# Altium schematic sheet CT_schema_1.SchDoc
size 596 x 258 mm
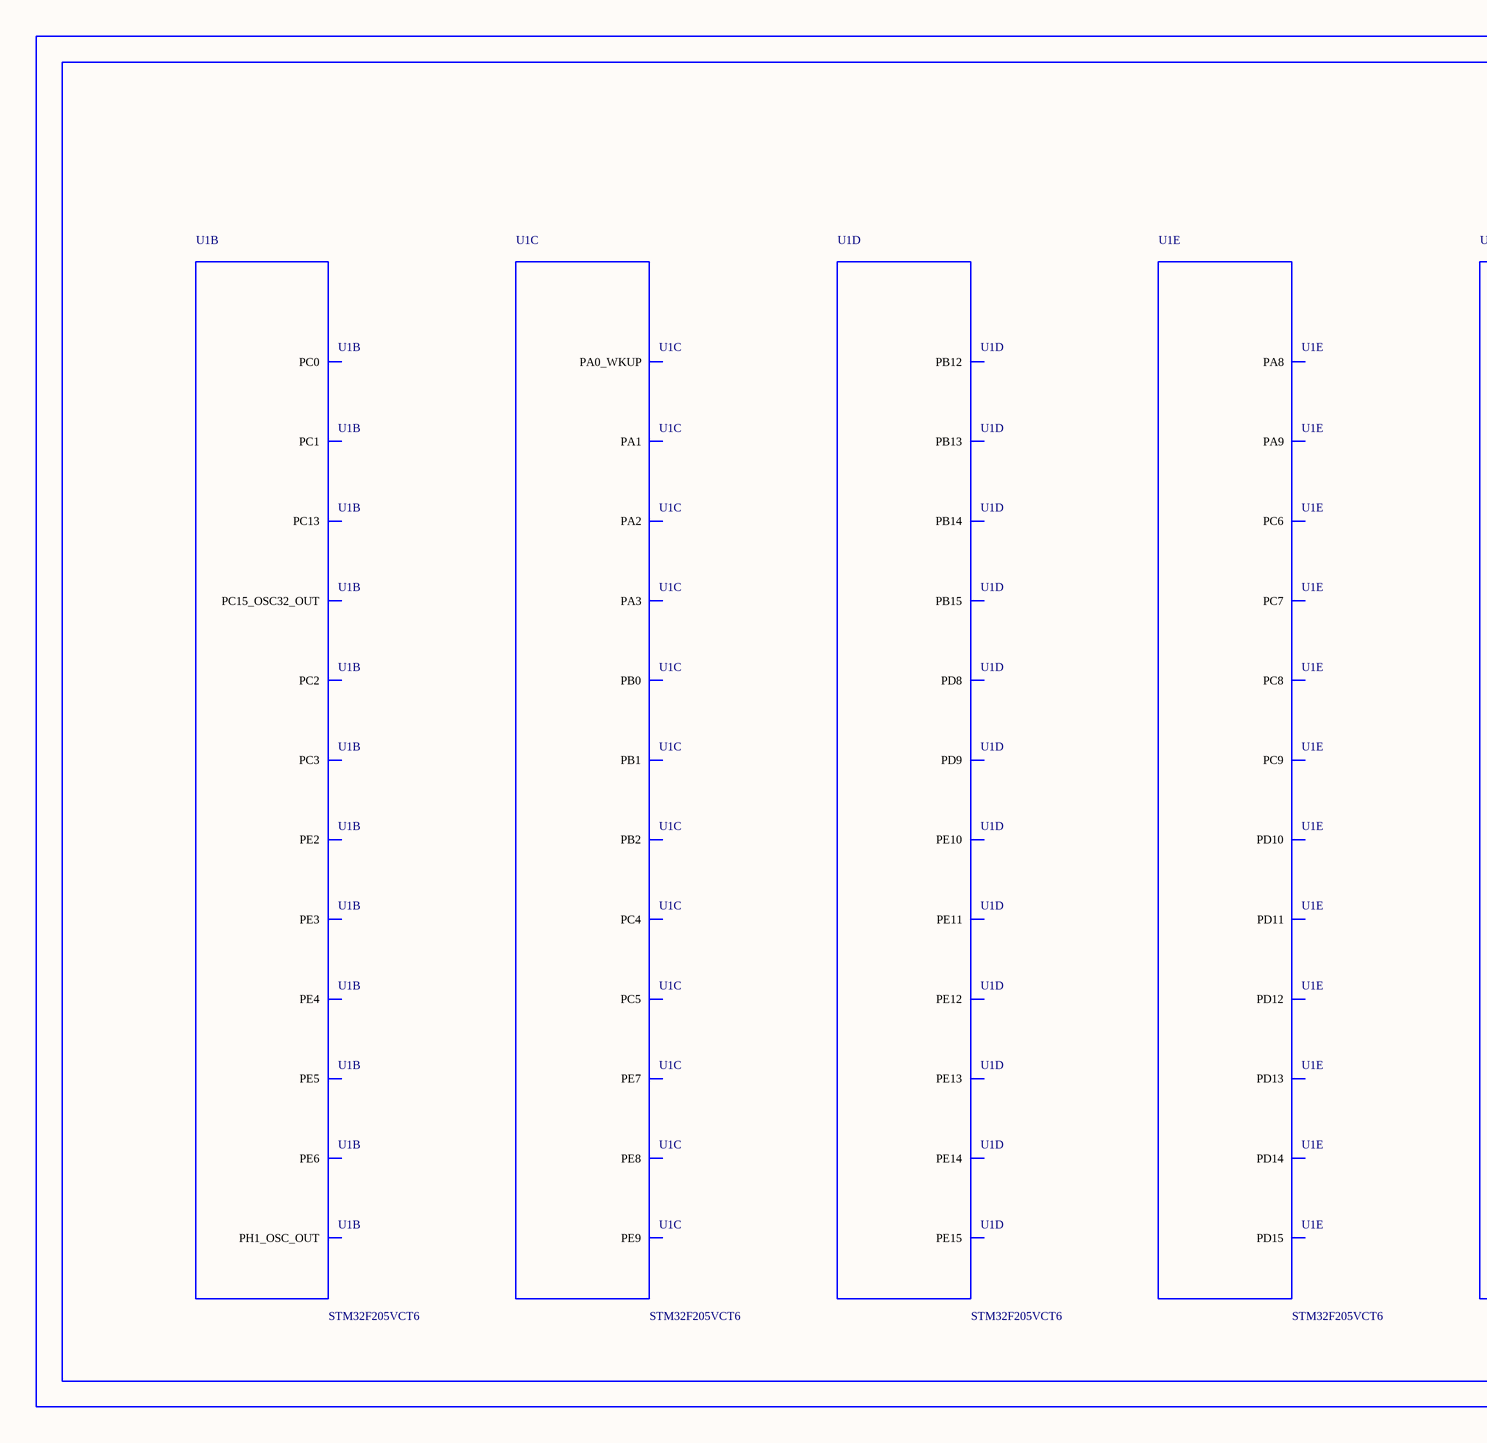
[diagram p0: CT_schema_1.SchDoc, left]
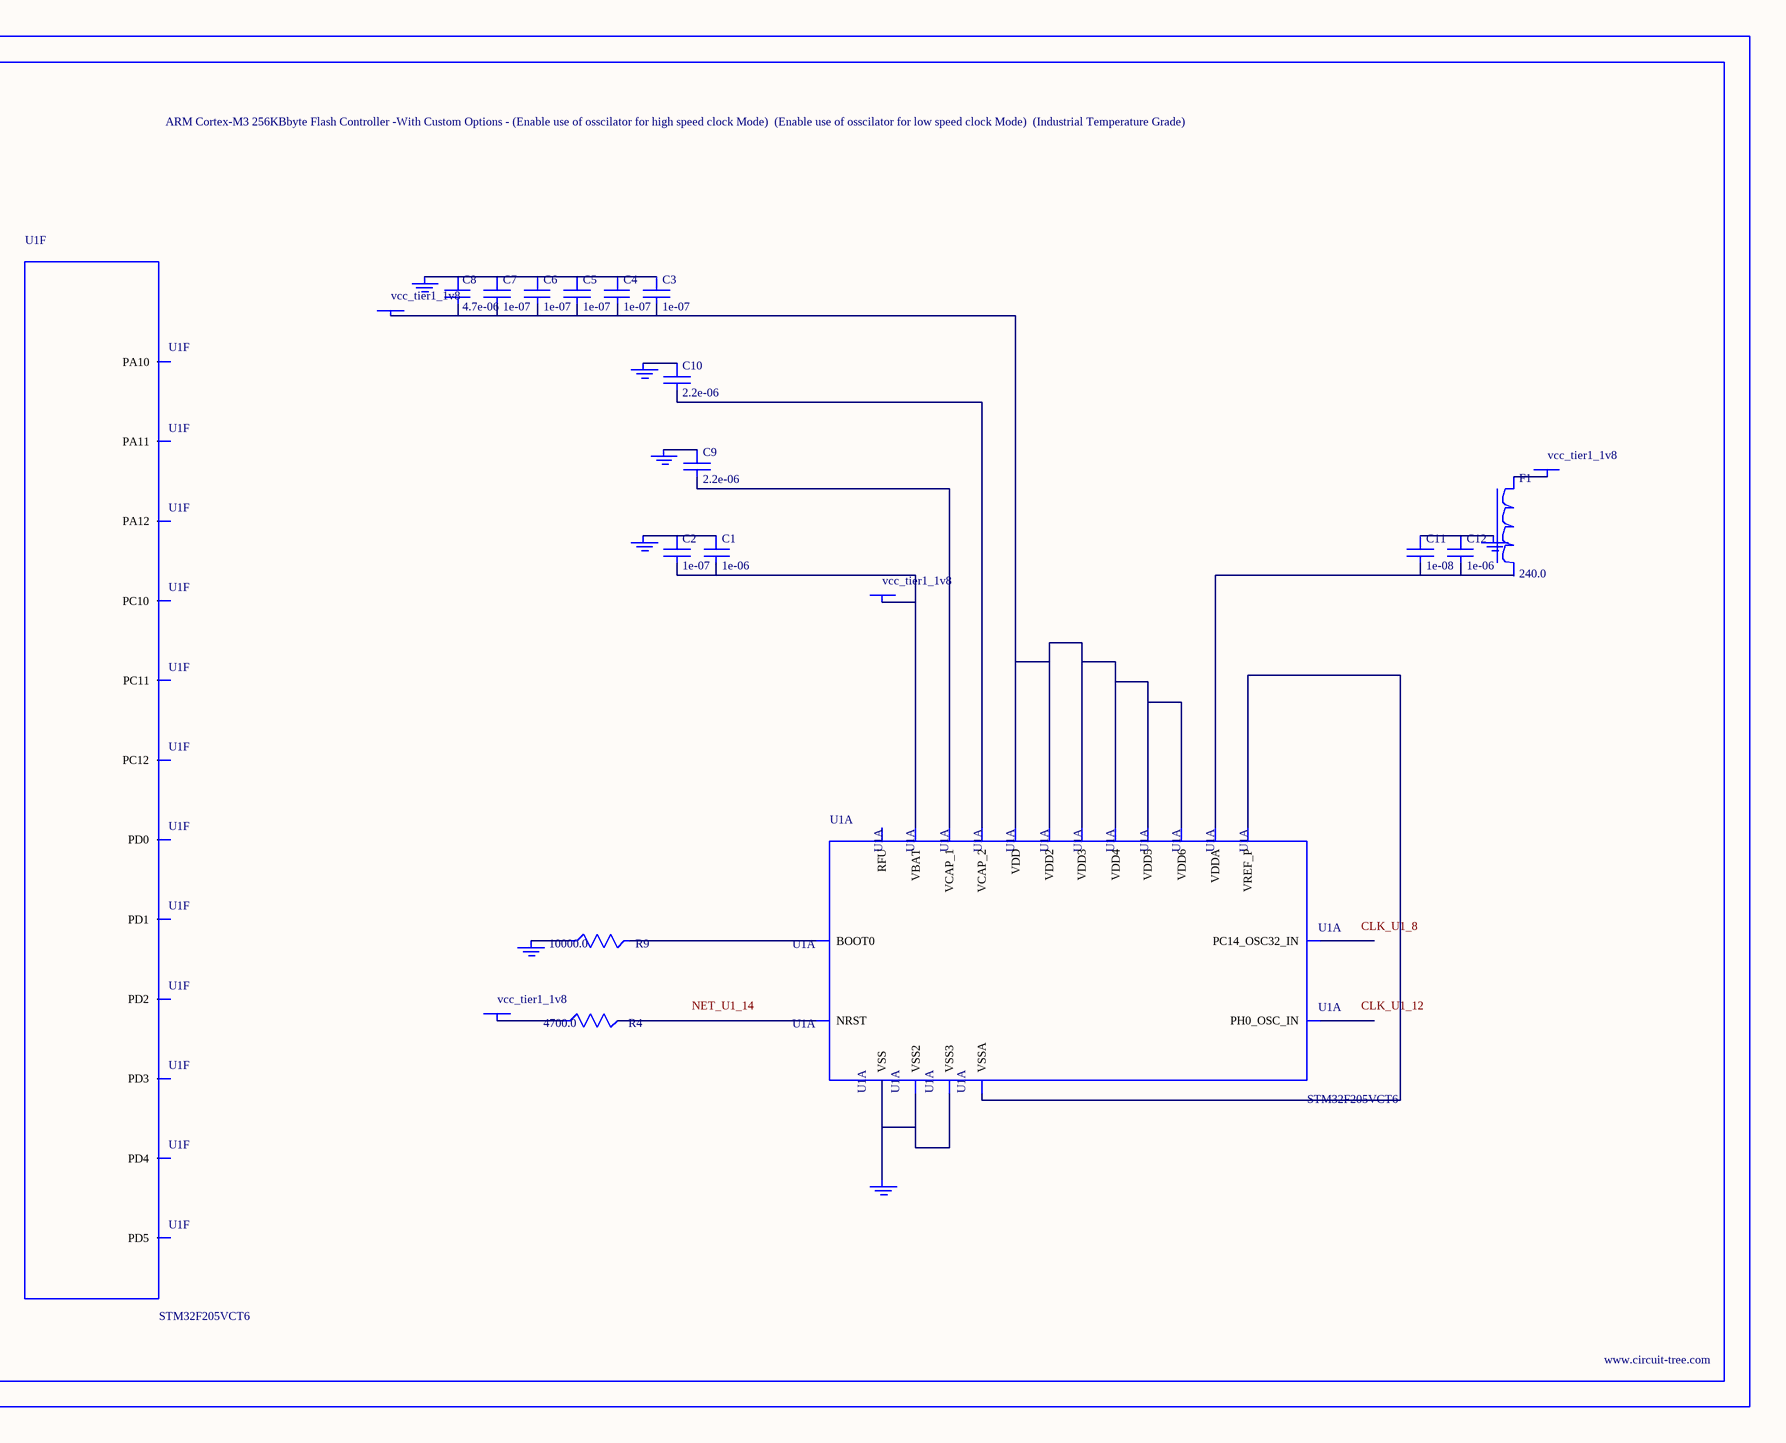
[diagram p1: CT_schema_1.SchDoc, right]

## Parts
BORDER0  (no value)
C1  1e-06  [C0603]
C2  1e-07  [C0603]
C3  1e-07  [C0603]
C4  1e-07  [C0603]
C5  1e-07  [C0603]
C6  1e-07  [C0603]
C7  1e-07  [C0603]
C8  4.7e-06  [C0603]
C9  2.2e-06  [C0603]
C10  2.2e-06  [C0603]
C11  1e-08  [C0603]
C12  1e-06  [C0603]
F1  240.0  [L0603]
GND_INSTANCE_0_0  (no value)
GND_INSTANCE_0_1  (no value)
GND_INSTANCE_0_2  (no value)
GND_INSTANCE_0_3  (no value)
GND_INSTANCE_0_4  (no value)
GND_INSTANCE_0_5  (no value)
GND_INSTANCE_0_6  (no value)
POWER_INSTANCE_0_0  vcc_tier1_1v8
POWER_INSTANCE_0_1  vcc_tier1_1v8
POWER_INSTANCE_0_2  vcc_tier1_1v8
POWER_INSTANCE_0_3  vcc_tier1_1v8
R4  4700.0  [R0603]
R9  10000.0  [R0603]
U1  STM32F205VCT6  [LQFP100]  (parts A,B,C,D,E,F of 10)

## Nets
NetC1_1: C1.1 C2.1 GND_INSTANCE_0_0.0(GND)
NetC1_2: C1.2 C2.2 POWER_INSTANCE_0_0.0(PWR) U1.6(VBAT)
NetC3_1: C3.1 C4.1 C5.1 C6.1 C7.1 C8.1 GND_INSTANCE_0_1.0(GND)
NetC3_2: C3.2 C4.2 C5.2 C6.2 C7.2 C8.2 POWER_INSTANCE_0_1.0(PWR) U1.11(VDD) U1.19(VDD2) U1.28(VDD3) U1.50(VDD4) U1.75(VDD5) U1.100(VDD6)
NetC9_1: C9.1 GND_INSTANCE_0_3.0(GND)
NetC9_2: C9.2 U1.49(VCAP_1)
NetC10_1: C10.1 GND_INSTANCE_0_4.0(GND)
NetC10_2: C10.2 U1.73(VCAP_2)
NetC11_1: C11.1 C12.1 GND_INSTANCE_0_2.0(GND)
NetC11_2: C11.2 C12.2 U1.22(VDDA)
NetF1_1: F1.1 POWER_INSTANCE_0_2.0(PWR)
NetGND_INSTANCE_0_5_0: GND_INSTANCE_0_5.0(GND) R9.1
NetGND_INSTANCE_0_6_0: GND_INSTANCE_0_6.0(GND) U1.10(VSS) U1.27(VSS2) U1.74(VSS3)
NetPOWER_INSTANCE_0_3_0: POWER_INSTANCE_0_3.0(PWR) R4.1
NetR4_2: R4.2 U1.14(NRST)
NetR9_2: R9.2 U1.94(BOOT0)
NetU1_20: U1.20(VSSA) U1.21(VREF_P)

Not connected (* = marked no-connect by the designer): F1 2; U1 1(PE2) 2(PE3) 3(PE4) 4(PE5) 5(PE6) 7(PC13) 8(PC14_OSC32_IN) 9(PC15_OSC32_OUT) 12(PH0_OSC_IN) 13(PH1_OSC_OUT) 15(PC0) 16(PC1) 17(PC2) 18(PC3) 23(PA0_WKUP) 24(PA1) 25(PA2) 26(PA3) 33(PC4) 34(PC5) 35(PB0) 36(PB1) 37(PB2) 38(PE7) 39(PE8) 40(PE9) 41(PE10) 42(PE11) 43(PE12) 44(PE13) 45(PE14) 46(PE15) 51(PB12) 52(PB13) 53(PB14) 54(PB15) 55(PD8) 56(PD9) 57(PD10) 58(PD11) 59(PD12) 60(PD13) 61(PD14) 62(PD15) 63(PC6) 64(PC7) 65(PC8) 66(PC9) 67(PA8) 68(PA9) 69(PA10) 70(PA11) 71(PA12) 78(PC10) 79(PC11) 80(PC12) 81(PD0) 82(PD1) 83(PD2) 84(PD3) 85(PD4) 86(PD5) 99(RFU)

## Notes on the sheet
- Labels drawn without touching a wire or pin: CLK_U1_8, CLK_U1_12, NET_U1_14

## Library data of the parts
BORDER0 = BORDER_PAGE0
C1 C12 = C0603C105K3RACTU
C2-C7 = 06035C104K4Z2A
C8 = GRM188R6YA475KE15D
C9 C10 = C0603C225K8RACTU
C11 = 06035C103K4Z2A
F1 = Z0603C241ASMST
GND_INSTANCE_0_0-GND_INSTANCE_0_6 = GND
POWER_INSTANCE_0_0-POWER_INSTANCE_0_3 = PWR
R4 = RC0603JR-074K7L
R9 = RC0603JR-0710KL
